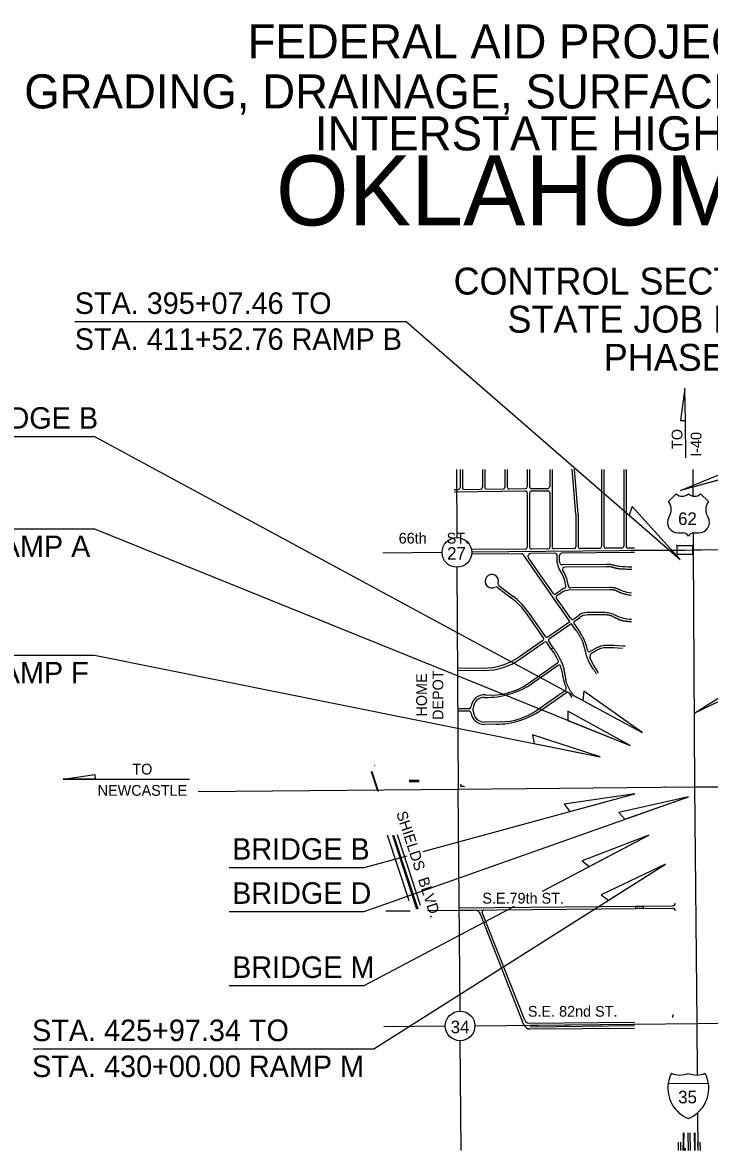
# Model space of a CAD drawing. Extents: x 2121385 to 2181200, y 132498 to 161273.
# Drawn here: x 2143424 to 2151083, y 138945 to 151519 of the extents above; entities that cross this region are included whole.
import ezdxf

# ---------------------------------------------------------------- set-up
doc = ezdxf.new("R2010")
doc.units = 0
for name, color, linetype in [('4', 7, 'Continuous'), ('5', 7, 'Continuous'), ('7', 7, 'Continuous'), ('Default', 7, 'Continuous'), ('ex-roads', 7, 'Continuous'), ('Level 3', 7, 'Continuous'), ('SEC', 7, 'Continuous'), ('SHT_Standard_Sheet_Txt', 7, 'Continuous')]:
    doc.layers.add(name, color=color, linetype=linetype)

msp = doc.modelspace()

# ---------------------------------------------------------------- linework, layer by layer
at = {"layer": '5'}
for p, q in [((2150821, 146666), (2150815, 147081)), ((2143876, 143083), (2145284, 143083))]:
    msp.add_line(p, q, dxfattribs=at)
for points in [[(2144008, 148185), (2147700, 148185), (2150756, 145535)], [(2158370, 147501), (2155118, 147501), (2150761, 146303)], [(2142737, 146905), (2144226, 146905), (2150332, 143606)], [(2140533, 145876), (2144226, 145876), (2150201, 143459)], [(2158636, 145838), (2155118, 145838), (2150917, 143820)], [(2140533, 144467), (2144226, 144467), (2149865, 143332)], [(2145726, 141609), (2147234, 141609), (2150849, 142887)], [(2147891, 142279), (2150251, 142921)], [(2149223, 141836), (2150406, 142461)], [(2145726, 142101), (2147234, 142101), (2147712, 142231)], [(2143543, 140079), (2147340, 140079), (2150593, 142136)], [(2145726, 140783), (2147234, 140783), (2148910, 141670)]]:
    msp.add_lwpolyline(points, dxfattribs=at)
for points in [[(2150810, 147440), (2150761, 147083), (2150815, 147081)], [(2150761, 146303), (2151497, 146603), (2151484, 146501)], [(2150756, 145535), (2150221, 146124), (2150189, 146027)], [(2150917, 143820), (2151588, 144247), (2151593, 144145)], [(2150332, 143606), (2149683, 144065), (2149673, 143963)], [(2150201, 143459), (2149504, 143842), (2149505, 143740)], [(2149865, 143332), (2149109, 143580), (2149129, 143480)], [(2143876, 143083), (2144231, 143138), (2144234, 143085)], [(2150251, 142921), (2149464, 142805), (2149527, 142724)], [(2150849, 142887), (2150073, 142713), (2150141, 142637)], [(2150406, 142461), (2149664, 142175), (2149743, 142111)], [(2150593, 142136), (2149875, 141794), (2149959, 141735)]]:
    msp.add_lwpolyline(points, close=True, dxfattribs=at)
for centre in [(2148267, 145612), (2148303, 140333)]:
    msp.add_circle(centre, 165, dxfattribs=at)
at = {"layer": '7'}
msp.add_line((2150624, 139695), (2151073, 139692), dxfattribs=at)
for points in [[(2150713, 146265), (2150628, 146179)], [(2151071, 146179), (2150985, 146265)], [(2150733, 145829), (2150791, 145829)], [(2150908, 145829), (2150966, 145829)]]:
    msp.add_lwpolyline(points, dxfattribs=at)
for centre, radius, start, end in [((2150780, 146335), 97.3, 226.4568, 314.9997), ((2150918, 146335), 97.3, 225.0003, 313.5432), ((2150502, 146088), 155, 326.2654, 35.69), ((2151197, 146088), 155, 144.3103, 213.7344), ((2150733, 145946), 117, 150.9454, 270), ((2150966, 145946), 117, 270, 29.0546), ((2150791, 145764), 65.2, 26.5657, 90), ((2150908, 145764), 65.2, 90, 153.4343), ((2150988, 139640), 368, 153.4721, 171.4449), ((2150754, 140037), 251, 247.4926, 291.8014), ((2150941, 140037), 251, 248.1986, 292.5074), ((2150708, 139640), 368, 8.103, 26.5279), ((2150988, 139640), 368, 171.4449, 247.6594), ((2150708, 139640), 368, 292.3406, 8.103)]:
    msp.add_arc(centre, radius, start, end, dxfattribs=at)
at = {"layer": 'Default'}
for p, q in [((2150588, 143003), (2150588, 142999)), ((2150761, 142998), (2150761, 142998)), ((2150624, 139695), (2151073, 139692))]:
    msp.add_line(p, q, dxfattribs=at)
for centre, radius, start, end in [((2150988, 139640), 368, 153.4721, 171.4449), ((2150754, 140037), 251, 247.4926, 291.8014), ((2150941, 140037), 251, 248.1986, 292.5074), ((2150708, 139640), 368, 8.103, 26.5279)]:
    msp.add_arc(centre, radius, start, end, dxfattribs=at)
at = {"layer": 'ex-roads'}
for p, q in [((2148302, 146535), (2148302, 146335)), ((2148328, 146535), (2148328, 146335)), ((2148552, 146535), (2148552, 146338)), ((2148578, 146535), (2148578, 146338)), ((2148802, 146535), (2148802, 146340)), ((2148828, 146535), (2148828, 146341)), ((2149052, 146535), (2149052, 146343)), ((2149078, 146535), (2149078, 146344)), ((2149302, 146535), (2149302, 146346)), ((2149328, 146535), (2149328, 145672)), ((2149594, 146040), (2149552, 146539)), ((2149620, 146040), (2149578, 146539)), ((2149881, 146535), (2149881, 145677)), ((2149907, 146535), (2149907, 145678)), ((2150128, 146535), (2150128, 145680)), ((2150154, 146535), (2150154, 145680)), ((2148237, 146314), (2148282, 146315)), ((2148237, 146288), (2149032, 146297)), ((2148348, 146315), (2148532, 146318)), ((2148598, 146318), (2148782, 146320)), ((2148848, 146321), (2149032, 146323)), ((2149052, 146277), (2149052, 145669)), ((2149078, 146278), (2149078, 145670)), ((2149098, 146324), (2149282, 146326)), ((2149098, 146298), (2149282, 146300)), ((2149302, 146280), (2149302, 145671)), ((2149594, 146040), (2149594, 145674)), ((2149620, 146040), (2149620, 145675)), ((2149032, 145649), (2148429, 145643)), ((2149282, 145651), (2149098, 145650)), ((2149574, 145654), (2149348, 145652)), ((2150206, 145611), (2149437, 145603)), ((2149861, 145657), (2149640, 145655)), ((2150108, 145660), (2149927, 145658)), ((2150206, 145661), (2150174, 145660)), ((2150247, 145661), (2150206, 145661)), ((2150206, 145636), (2150809, 145639)), ((2150247, 145611), (2150206, 145611)), ((2150723, 145689), (2150715, 145697)), ((2150723, 145689), (2150894, 145690)), ((2150723, 145639), (2150723, 145689)), ((2150723, 145589), (2150723, 145639)), ((2150809, 145639), (2150906, 145640)), ((2150894, 145690), (2150902, 145698)), ((2150894, 145690), (2150895, 145640)), ((2150895, 145640), (2150895, 145590)), ((2150906, 145640), (2150999, 145640)), ((2148985, 145598), (2148430, 145593)), ((2149528, 144842), (2149009, 145586)), ((2149133, 145454), (2149064, 145552)), ((2149361, 145602), (2149089, 145599)), ((2149387, 145505), (2149386, 145577)), ((2149404, 145437), (2149387, 145505)), ((2149413, 145509), (2149412, 145578)), ((2149417, 145493), (2149413, 145509)), ((2150723, 145589), (2150716, 145581)), ((2150895, 145590), (2150723, 145589)), ((2150895, 145590), (2150903, 145582)), ((2149340, 145156), (2149133, 145454)), ((2149440, 145375), (2149404, 145437)), ((2149468, 145309), (2149440, 145375)), ((2149930, 145479), (2149441, 145474)), ((2149463, 145387), (2149449, 145411)), ((2149493, 145317), (2149463, 145387)), ((2149930, 145453), (2149471, 145448)), ((2148735, 145245), (2148890, 145126)), ((2149482, 145244), (2149468, 145309)), ((2149510, 145240), (2149493, 145317)), ((2148718, 145225), (2148874, 145106)), ((2149368, 145151), (2149421, 145188)), ((2149383, 145130), (2149429, 145162)), ((2149972, 145195), (2149517, 145190)), ((2149972, 145221), (2149539, 145216)), ((2149538, 144874), (2149378, 145102)), ((2149232, 144661), (2149054, 144916)), ((2149254, 144676), (2149076, 144931)), ((2149565, 144869), (2149631, 144914)), ((2149580, 144847), (2149639, 144888)), ((2149889, 144944), (2149718, 144942)), ((2149890, 144918), (2149727, 144916)), ((2149282, 144671), (2149528, 144842)), ((2149296, 144649), (2149543, 144821)), ((2149598, 144742), (2149543, 144821)), ((2149619, 144757), (2149575, 144819)), ((2148967, 144451), (2149227, 144633)), ((2148969, 144421), (2149242, 144612)), ((2149320, 144535), (2149270, 144607)), ((2149341, 144550), (2149291, 144622)), ((2149341, 144550), (2149320, 144535)), ((2149767, 144484), (2149755, 144471)), ((2149062, 144152), (2149390, 144381)), ((2149115, 144157), (2149398, 144354)), ((2148560, 144321), (2148280, 144318)), ((2148576, 144295), (2148280, 144292)), ((2149158, 143853), (2149478, 144076)), ((2149211, 143858), (2149489, 144052)), ((2148404, 143869), (2148285, 143868)), ((2148449, 143845), (2148449, 143871)), ((2148404, 143843), (2148285, 143842)), ((2148751, 143723), (2148574, 143721)), ((2148705, 143697), (2148575, 143695)), ((2147348, 143238), (2147349, 143234)), ((2147315, 143167), (2147319, 143168)), ((2147386, 142949), (2147315, 143167)), ((2147319, 143168), (2147390, 142950)), ((2147390, 142950), (2147386, 142949)), ((2147735, 141726), (2147494, 142461)), ((2147549, 142461), (2147818, 141640)), ((2147561, 142461), (2147830, 141640)), ((2147670, 142258), (2147603, 142462)), ((2147862, 141674), (2147670, 142258)), ((2147475, 141616), (2147745, 141618)), ((2147941, 141620), (2150263, 141643)), ((2148293, 141650), (2150263, 141669)), ((2148293, 141624), (2148460, 141625)), ((2149023, 140397), (2148550, 141599)), ((2150263, 141643), (2150263, 141669)), ((2150263, 141669), (2150349, 141669)), ((2150349, 141643), (2150263, 141643)), ((2150349, 141669), (2150672, 141672)), ((2150349, 141643), (2150349, 141669)), ((2150349, 141643), (2150674, 141646)), ((2149015, 140347), (2148531, 141578)), ((2150676, 140428), (2150678, 140460)), ((2149070, 140365), (2150249, 140376)), ((2149083, 140343), (2150249, 140354)), ((2150249, 140333), (2149083, 140321)), ((2149085, 140299), (2150249, 140310)), ((2150849, 138945), (2150847, 139142)), ((2150871, 138945), (2150869, 139142)), ((2150919, 138945), (2150917, 139142)), ((2150925, 138945), (2150923, 139143)), ((2150738, 138945), (2150737, 139039)), ((2150764, 138945), (2150763, 139039)), ((2150811, 138972), (2150811, 138945)), ((2150956, 138945), (2150955, 139039)), ((2150982, 138945), (2150981, 139039))]:
    msp.add_line(p, q, dxfattribs=at)
for points in [[(2149948, 145479), (2149930, 145479)], [(2149965, 145478), (2149949, 145479)], [(2149980, 145476), (2149966, 145478)], [(2149993, 145474), (2149981, 145476)], [(2150006, 145471), (2149995, 145474)], [(2150017, 145469), (2150007, 145471)], [(2150028, 145466), (2150018, 145468)], [(2150219, 145447), (2150175, 145449), (2150139, 145450), (2150111, 145452), (2150089, 145454), (2150072, 145456), (2150058, 145458), (2150048, 145461), (2150038, 145463), (2150028, 145466)], [(2149989, 145220), (2149972, 145221)], [(2150005, 145219), (2149990, 145220)], [(2150019, 145217), (2150007, 145219)], [(2150032, 145215), (2150021, 145217)], [(2150044, 145211), (2150034, 145214)], [(2150055, 145207), (2150046, 145210)], [(2150066, 145202), (2150056, 145206)], [(2150216, 145158), (2150188, 145162), (2150164, 145167), (2150144, 145172), (2150126, 145177), (2150111, 145182), (2150098, 145187), (2150087, 145192), (2150076, 145197), (2150066, 145202)], [(2149918, 144943), (2149890, 144944)], [(2149944, 144940), (2149920, 144943)], [(2149969, 144935), (2149946, 144940)], [(2149991, 144929), (2149971, 144935)], [(2150011, 144922), (2149993, 144929)], [(2150030, 144914), (2150012, 144921)], [(2150047, 144906), (2150031, 144914)], [(2150216, 144863), (2150188, 144865), (2150164, 144868), (2150144, 144872), (2150125, 144876), (2150108, 144881), (2150093, 144886), (2150078, 144892), (2150063, 144899), (2150047, 144906)], [(2149642, 144722), (2149619, 144756)], [(2149661, 144690), (2149643, 144721)], [(2149677, 144660), (2149662, 144689)], [(2149689, 144633), (2149677, 144659)], [(2149699, 144607), (2149690, 144631)], [(2149708, 144581), (2149700, 144605)], [(2149401, 144398), (2149381, 144438), (2149354, 144484), (2149320, 144536)], [(2149715, 144557), (2149708, 144580)], [(2149726, 144516), (2149721, 144532), (2149715, 144556)], [(2149830, 144551), (2149754, 144507)], [(2150115, 144541), (2150063, 144544), (2150017, 144548), (2149976, 144550), (2149939, 144550), (2149905, 144547), (2149873, 144540), (2149843, 144529), (2149767, 144484)], [(2149864, 144564), (2149834, 144553)], [(2149899, 144572), (2149868, 144566)], [(2149936, 144575), (2149902, 144573)], [(2149976, 144576), (2149939, 144576)], [(2150018, 144573), (2149977, 144575)], [(2150143, 144568), (2150117, 144567), (2150065, 144570), (2150019, 144573)], [(2149848, 144271), (2149817, 144317), (2149792, 144357), (2149772, 144393), (2149756, 144426), (2149748, 144446)], [(2149453, 144217), (2149448, 144243), (2149443, 144270), (2149436, 144299), (2149428, 144329), (2149421, 144348)], [(2149458, 144190), (2149453, 144216)], [(2149466, 144162), (2149459, 144189)], [(2149475, 144133), (2149466, 144161)], [(2149485, 144109), (2149476, 144131)], [(2149526, 144032), (2149518, 144046)], [(2149553, 143993), (2149527, 144031)]]:
    msp.add_lwpolyline(points, dxfattribs=at)
for centre, radius, start, end in [((2148282, 146335), 20, 270.672, 0), ((2148348, 146335), 20, 180, 270.672), ((2148532, 146338), 20, 270.672, 0), ((2148598, 146338), 20, 180, 270.672), ((2148782, 146340), 20, 270.672, 0), ((2148848, 146341), 20, 180, 270.672), ((2149032, 146343), 20, 270.672, 0), ((2149032, 146277), 20, 0, 90.672), ((2149098, 146344), 20, 180, 270.672), ((2149098, 146278), 20, 90.672, 180), ((2149282, 146346), 20, 270.672, 0), ((2149282, 146280), 20, 0, 90.672), ((2149032, 145669), 20, 270.5834, 0), ((2149098, 145670), 20, 180, 270.5834), ((2149282, 145671), 20, 270.5834, 0), ((2149348, 145672), 20, 180, 270.5834), ((2149574, 145674), 20, 270.5834, 0), ((2149640, 145675), 20, 180, 270.5834), ((2149861, 145677), 20, 270.5834, 0), ((2149927, 145678), 20, 180, 270.5834), ((2150108, 145680), 20, 270.5834, 0), ((2150174, 145680), 20, 180, 270.5834), ((2148985, 145568), 30, 34.8836, 90.5834), ((2149089, 145569), 30, 90.5834, 214.8836), ((2149361, 145577), 25, 0.3443, 90.5834), ((2149437, 145578), 25, 90.5834, 180.3443), ((2149441, 145499), 25, 194.3471, 270.5834), ((2148657, 145291), 75, 341.3907, 143.3106), ((2149471, 145423), 25, 90.5834, 210.0011), ((2149947, 145453), 26, 86.6037, 89.3323), ((2149963, 145452), 26, 83.6947, 86.6037), ((2149977, 145450), 26, 80.7788, 83.6947), ((2149989, 145448), 26, 78.1174, 80.7788), ((2150001, 145446), 26, 76.0288, 78.1174), ((2150011, 145443), 26, 74.8192, 76.0288), ((2150021, 145441), 26, 74.693, 74.8192), ((2148657, 145291), 75, 143.3106, 300.731), ((2148747, 145261), 20, 161.3907, 232.0892), ((2149453, 145237), 30, 287.8237, 12.4069), ((2149539, 145246), 30, 192.4069, 270.5834), ((2148706, 145209), 20, 52.0892, 120.731), ((2148337, 144416), 900, 34.8836, 52.0892), ((2149357, 145168), 20, 214.8836, 304.8836), ((2149395, 145114), 20, 124.8836, 214.8836), ((2149510, 145060), 156, 107.8237, 124.8836), ((2149518, 145034), 156, 90.5834, 124.8836), ((2149988, 145194), 26, 85.8179, 89.1742), ((2150003, 145193), 26, 81.7926, 85.8179), ((2150015, 145192), 26, 77.3116, 81.7926), ((2150026, 145189), 26, 72.8382, 77.3116), ((2150036, 145186), 26, 68.9981, 72.8382), ((2150046, 145182), 26, 66.3433, 68.9981), ((2150056, 145178), 26, 65.1301, 66.3433), ((2148337, 144416), 874, 34.8836, 52.0892), ((2149554, 144885), 20, 214.8836, 304.8836), ((2149720, 144786), 156, 90.5834, 124.8836), ((2149728, 144760), 156, 90.5834, 124.8836), ((2149917, 144917), 26, 83.4684, 88.2729), ((2149941, 144914), 26, 78.6835, 83.4684), ((2149964, 144910), 26, 74.1948, 78.6835), ((2149984, 144904), 26, 70.3093, 74.1948), ((2150002, 144897), 26, 67.3261, 70.3093), ((2150020, 144890), 26, 65.5077, 67.3261), ((2150036, 144883), 26, 65.065, 65.5077), ((2149592, 144831), 20, 124.8836, 214.8836), ((2149216, 144649), 20, 304.8836, 34.8836), ((2149254, 144595), 20, 34.8836, 124.8836), ((2149270, 144687), 20, 214.8836, 304.8836), ((2149308, 144633), 20, 124.8836, 214.8836), ((2149620, 144708), 26, 30.8238, 33.6367), ((2149639, 144677), 26, 27.6628, 30.8238), ((2149654, 144648), 26, 24.3006, 27.6628), ((2149666, 144622), 26, 20.9989, 24.3006), ((2149675, 144597), 26, 18.1084, 20.9989), ((2149683, 144573), 26, 15.9854, 18.1084), ((2149690, 144550), 26, 14.8834, 15.9854), ((2149744, 144524), 20, 204.5242, 300.3371), ((2149843, 144529), 25.9, 110.7937, 120.3371), ((2149873, 144540), 25.9, 101.8868, 110.7937), ((2149905, 144547), 25.9, 94.7771, 101.8868), ((2149939, 144550), 25.9, 89.9105, 94.7771), ((2149976, 144550), 25.9, 87.139, 89.9105), ((2150017, 144548), 25.9, 86.062, 87.139), ((2148553, 145045), 724, 270.5834, 304.8836), ((2148569, 144995), 700, 270.5834, 304.8836), ((2149379, 144397), 20, 304.8836, 26.8824), ((2149407, 144339), 17.3, 31.8225, 119.6819), ((2149770, 144453), 22.5, 128.7976, 199.318), ((2148600, 144896), 900, 268.4615, 304.8836), ((2148648, 144746), 724, 265.0559, 304.8836), ((2149478, 144222), 26, 190.5756, 191.8793), ((2149484, 144195), 26, 191.8793, 194.5461), ((2149491, 144169), 26, 194.5461, 198.2421), ((2149500, 144141), 26, 198.2421, 202.481), ((2149457, 144098), 30.2, 313.3267, 21.159), ((2148573, 143875), 150, 85.0559, 175.2046), ((2148573, 143872), 124, 88.4615, 180.3018), ((2149501, 144036), 20, 30.7767, 124.8836), ((2149549, 144046), 26, 210.7767, 214.2876), ((2148403, 143889), 20, 270.5834, 355.2046), ((2148696, 144596), 900, 270.5834, 304.8836), ((2148744, 144447), 724, 270.5834, 304.8836), ((2148404, 143823), 20, 7.3397, 90.5834), ((2148573, 143845), 150, 187.3397, 270.5834), ((2148573, 143845), 124, 180.3018, 270.5834), ((2148461, 141550), 75, 21.4756, 90.5516), ((2148569, 141606), 20, 90.5516, 201.4756), ((2150672, 141702), 30, 270.5516, 0.7086), ((2150674, 141616), 30, 1.6469, 90.5516), ((2149085, 140374), 75, 201.4756, 270.5516), ((2149070, 140415), 50, 201.4756, 270.5516), ((2151036, 143300), 3851, 264.4141, 264.4313), ((2147935, 139116), 2859, 356.5627, 0.5015), ((2147941, 139116), 2859, 356.5627, 0.5015), ((2147685, 139066), 3127, 357.7779, 358.2718)]:
    msp.add_arc(centre, radius, start, end, dxfattribs=at)
for points in [[(2150218, 145421), (2150088, 145425), (2150028, 145437), (2149980, 145454), (2149930, 145453)], [(2150212, 145132), (2150130, 145144), (2150056, 145178), (2150020, 145195), (2149972, 145195)], [(2150214, 144837), (2150134, 144842), (2150055, 144870), (2149966, 144919), (2149890, 144918)], [(2149827, 144257), (2149733, 144386), (2149694, 144535), (2149665, 144646), (2149598, 144742)], [(2149575, 144008), (2149497, 144115), (2149476, 144238), (2149444, 144402), (2149341, 144550)]]:
    msp.add_open_spline(points, degree=2, dxfattribs=at)
at = {"layer": 'Level 3'}
for p, q in [((2147733, 143075), (2147848, 143072)), ((2147733, 143065), (2147848, 143066)), ((2147733, 143063), (2147848, 143064)), ((2147733, 143053), (2147848, 143057)), ((2148310, 143027), (2148309, 143003))]:
    msp.add_line(p, q, dxfattribs=at)
msp.add_arc((2148062, 137337), 5671, 87.0443, 87.5046, dxfattribs=at)
at = {"layer": 'SEC'}
for p, q in [((2148261, 146535), (2148266, 145777)), ((2150902, 146239), (2150900, 146535)), ((2150906, 145639), (2150905, 145829)), ((2150906, 145639), (2150905, 145829)), ((2148102, 145612), (2147441, 145605)), ((2150906, 145639), (2148432, 145614)), ((2153390, 145653), (2150906, 145639)), ((2150922, 142997), (2150906, 145639)), ((2148268, 145447), (2148283, 142972)), ((2145382, 142945), (2148283, 142972)), ((2148283, 142972), (2150922, 142997)), ((2148302, 140498), (2148283, 142972)), ((2150922, 142997), (2153570, 143016)), ((2150945, 140359), (2150922, 142997)), ((2147453, 140327), (2148138, 140333)), ((2148468, 140335), (2150945, 140359)), ((2150945, 140359), (2153422, 140378)), ((2150950, 139786), (2150945, 140359)), ((2148313, 138945), (2148304, 140168)), ((2150957, 138945), (2150953, 139366))]:
    msp.add_line(p, q, dxfattribs=at)

# ---------------------------------------------------------------- texts
at = {"layer": '4'}
for s, p in [('STA. 395+07.46 TO', (2144006, 148271)), ('STA. 411+52.76 RAMP B', (2144006, 147870)), ('BRIDGE B', (2142732, 146991)), ('STA. 101+77.63 RAMP A', (2140531, 145560)), ('STA. 419+58.05 RAMP F', (2140531, 144152)), ('BRIDGE B', (2145761, 142186)), ('BRIDGE D', (2145761, 141694)), ('BRIDGE M', (2145761, 140868)), ('STA. 425+97.34 TO', (2143530, 140164)), ('STA. 430+00.00 RAMP M', (2143530, 139763))]:
    msp.add_text(s, height=240, dxfattribs=at).set_placement(p)
at = {"layer": '5'}
for s, p in [('62', (2150734, 145918)), ('27', (2148158, 145531)), ('34', (2148198, 140252)), ('35', (2150735, 139470))]:
    msp.add_text(s, height=140, dxfattribs=at).set_placement(p)
at = {"layer": 'SHT_Standard_Sheet_Txt'}
for s, height, p in [('FEDERAL AID PROJECT NO. NHPPI-0035-3(125)121', 380, (2145933, 151119)), ('GRADING, DRAINAGE, SURFACING, BRIDGE, & EROSION CONTROL PLANS', 380, (2143442, 150562)), ('INTERSTATE HIGHWAY NO. I-240 & I-35', 380, (2146684, 150094)), ('OKLAHOMA COUNTY', 780, (2146249, 149258)), ('CONTROL SECTION NO. 35-55-15', 300, (2148230, 148487)), ('STATE JOB NO. 09032(06)', 300, (2148831, 148062)), ('PHASE 2', 300, (2149905, 147637)), ('66th     ST.', 120, (2147618, 145711)), ('TO', 120, (2144648, 143136)), ('NEWCASTLE', 120, (2144261, 142899)), ('S.E.79th ST.', 120, (2148551, 141697)), ('S.E. 82nd ST.', 120, (2149059, 140436))]:
    msp.add_text(s, height=height, dxfattribs=at).set_placement(p)
for s, rotation, p in [('TO', 90, (2150782, 146765)), ('I-40', 90, (2150994, 146678)), ('HOME', 90, (2147933, 143782)), ('DEPOT', 90, (2148116, 143744)), ('SHIELDS  BLVD.', 288.1765, (2147589, 142705))]:
    msp.add_text(s, height=120, rotation=rotation, dxfattribs=at).set_placement(p)

doc.saveas('drawing.dxf')
